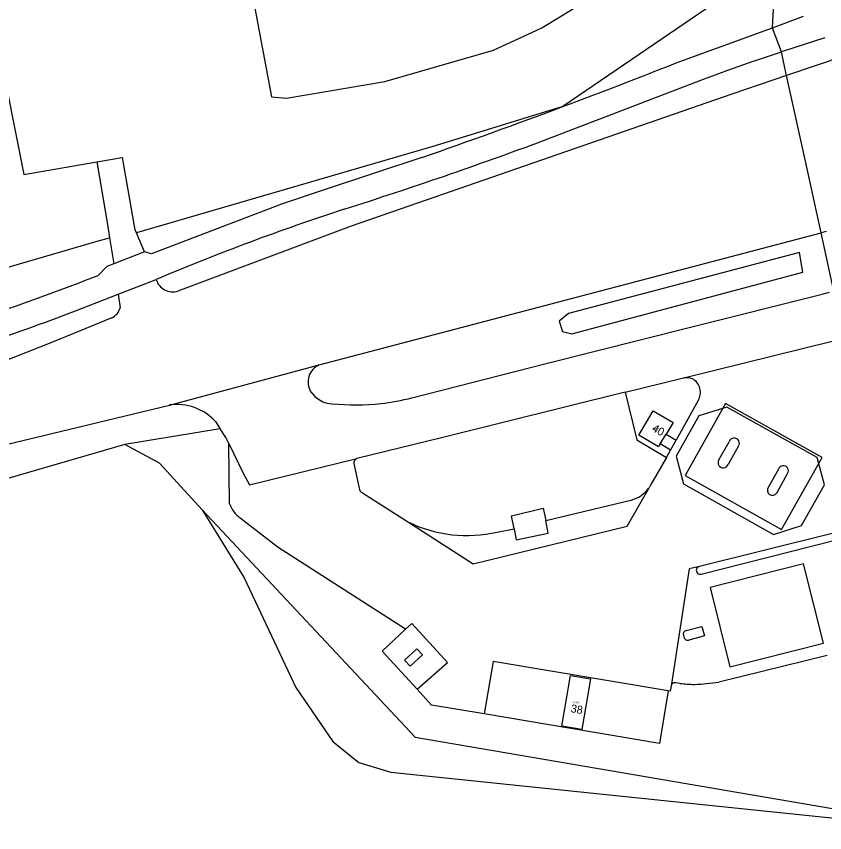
# Model space of a CAD drawing. Extents: x 124000 to 129000, y 395500 to 397503.
# Drawn here: x 124756.4 to 124856.7, y 396202 to 396303.2 of the extents above; entities that cross this region are included whole.
import ezdxf

# ---------------------------------------------------------------- set-up
doc = ezdxf.new("R2010")
doc.units = 0
for name, color, linetype in [('gg-anno-huisnummerreeks BGT', 7, 'Continuous'), ('gg-bbg-luifel en loopbrug', 7, 'Continuous'), ('gg-knt-verharding', 7, 'Continuous'), ('gg-kwrk-kunstwerk niveau 01', 7, 'Continuous'), ('gt-grn-vlakafsluiter', 7, 'Continuous'), ('gx-grn-maaiveld', 7, 'Continuous'), ('kenmerkpunt-x pandkandidaat', 7, 'Continuous')]:
    doc.layers.add(name, color=color, linetype=linetype)

msp = doc.modelspace()

# ---------------------------------------------------------------- linework, layer by layer
at = {"layer": 'gg-bbg-luifel en loopbrug'}
for points in [[(124837.26, 396219.54), (124815.51, 396223.21), (124814.41, 396216.7)], [(124826.53, 396214.76), (124824.07, 396215.17), (124825.13, 396221.46), (124827.6, 396221.05), (124826.53, 396214.76)], [(124837.26, 396219.54), (124836.16, 396213.03), (124814.41, 396216.7)]]:
    msp.add_lwpolyline(points, dxfattribs=at)
at = {"layer": 'gg-knt-verharding'}
for p, q in [((124850.18, 396301.8), (124854.06, 396303.23)), ((124856.69, 396300.56), (124851.3, 396298.84)), ((124865.47, 396300.5), (124851.95, 396295.88)), ((124856.85, 396276.55), (124856.23, 396276.39))]:
    msp.add_line(p, q, dxfattribs=at)
at = {"layer": 'gg-kwrk-kunstwerk niveau 01'}
for points in [[(124839.34, 396246.25), (124851.3, 396239.57), (124856.35, 396248.51), (124844.35, 396255.21), (124839.34, 396246.25)], [(124842.45, 396232.38), (124844.88, 396222.55), (124856.52, 396225.47), (124854.06, 396235.29), (124842.45, 396232.38)]]:
    msp.add_lwpolyline(points, dxfattribs=at)
at = {"layer": 'gt-grn-vlakafsluiter'}
msp.add_line((124857.82, 396269.12), (124856.23, 396276.39), dxfattribs=at)
at = {"layer": 'gx-grn-maaiveld'}
for p, q in [((124850.55, 396310.04), (124824.19, 396292.04)), ((124850.55, 396310.04), (124850.17, 396301.82)), ((124838.23, 396297.45), (124850.18, 396301.8)), ((124850.17, 396301.82), (124850.18, 396301.8)), ((124772.25, 396274.03), (124771.28, 396276.37)), ((124793.94, 396260), (124856.23, 396276.39)), ((124772.25, 396274.03), (124768.44, 396272.54)), ((124769.01, 396268.76), (124773.71, 396270.59)), ((124763.69, 396266.69), (124769.01, 396268.76)), ((124769.01, 396268.76), (124769.24, 396267.08)), ((124775.36, 396255.01), (124793.94, 396260)), ((124840.96, 396255.56), (124838.22, 396250.66)), ((124743.71, 396247.4), (124775.36, 396255.01)), ((124781.64, 396252.06), (124769.82, 396250.1)), ((124781.06, 396252.96), (124781.64, 396252.06)), ((124836.25, 396250.18), (124836.98, 396251.38)), ((124836.98, 396251.38), (124838.22, 396250.66)), ((124769.82, 396250.1), (124712.37, 396233.43)), ((124782.8, 396242.74), (124782.71, 396250.22)), ((124837.52, 396249.41), (124836.25, 396250.18)), ((124837.52, 396249.41), (124838.22, 396250.66)), ((124843.54, 396248.19), (124844.83, 396250.46)), ((124837.02, 396248.51), (124837.52, 396249.41)), ((124845.93, 396249.86), (124844.69, 396247.65)), ((124785.29, 396245.09), (124798.62, 396248.37)), ((124798.24, 396247.74), (124798.88, 396244.71)), ((124850.92, 396247.04), (124849.65, 396244.78)), ((124850.71, 396244.09), (124852.07, 396246.5)), ((124799.33, 396244.1), (124805.01, 396240.47)), ((124822.05, 396240.67), (124832.63, 396243.2)), ((124816.01, 396239.24), (124818.12, 396239.64)), ((124841.36, 396234.03), (124857.8, 396238.22)), ((124839.14, 396226.46), (124839.2, 396226.22)), ((124856.99, 396223.95), (124843.52, 396220.62)), ((124838.71, 396220.48), (124838.15, 396220.54))]:
    msp.add_line(p, q, dxfattribs=at)
for points in [[(124803.83, 396330.6), (124784.45, 396326.81), (124781.8, 396326.29), (124788.02, 396293.25), (124789.9, 396293.06), (124802.1, 396295.16), (124815.59, 396299.02), (124821.55, 396301.82), (124827.93, 396305.75), (124832.84, 396309.96), (124835.65, 396313.39), (124837.12, 396316.32), (124837.86, 396319.83), (124837.65, 396322.26), (124827.21, 396360.52), (124823.73, 396373.27), (124820.79, 396372.66), (124806.56, 396369.97), (124808.01, 396359.39), (124801.31, 396351.1), (124803.83, 396330.6)], [(124719.46, 396370.32), (124702.77, 396321.29), (124696.9, 396307.16), (124680.74, 396271.99), (124666.87, 396247.07), (124752.02, 396271.18), (124766.38, 396275.33), (124767.93, 396275.77)], [(124750.47, 396352.66), (124756.67, 396322.55), (124749.81, 396321.14), (124757.29, 396283.59), (124766.33, 396285.18)], [(124851.3, 396298.84), (124850.19, 396301.78), (124850.18, 396301.8)], [(124821.78, 396287.83), (124841.32, 396295.32), (124844.63, 396296.53), (124847.81, 396297.65), (124847.96, 396297.7), (124851.3, 396298.84)], [(124851.95, 396295.88), (124851.69, 396297.06), (124851.3, 396298.84)], [(124851.95, 396295.88), (124845.15, 396293.57), (124797.92, 396277.18), (124776.41, 396269.13)], [(124856.23, 396276.39), (124854.29, 396285.26), (124851.95, 396295.88)], [(124824.19, 396292.04), (124808.34, 396287.15), (124771.28, 396276.37)], [(124766.33, 396285.18), (124769.47, 396285.73), (124771.05, 396276.73), (124771.28, 396276.37)], [(124806.66, 396285.71), (124794.45, 396281.65), (124789.25, 396279.92), (124773.12, 396273.78), (124772.25, 396274.03)], [(124766.33, 396285.18), (124767.7, 396277.16), (124767.93, 396275.77)], [(124767.93, 396275.77), (124767.97, 396275.5), (124768.44, 396272.54)], [(124824.15, 396264.15), (124825.29, 396263.85), (124853.96, 396271.49), (124853.55, 396273.93), (124824.89, 396266.37), (124823.72, 396265.43), (124824.15, 396264.15)], [(124768.44, 396272.54), (124767.59, 396272.18), (124766.51, 396271.09)], [(124805.45, 396255.91), (124822.11, 396260.15), (124840.01, 396264.65), (124856.36, 396268.76), (124857.26, 396268.99)], [(124768.19, 396265.81), (124760.84, 396262.79), (124741.32, 396255.12), (124741.19, 396255.32), (124701.79, 396242.06)], [(124839.18, 396258.37), (124857.77, 396262.96), (124858.16, 396263.06)], [(124831.91, 396256.6), (124838.82, 396258.31), (124838.99, 396258.35), (124839.18, 396258.37)], [(124831.91, 396256.6), (124809.29, 396251), (124798.62, 396248.37)], [(124831.91, 396256.6), (124833.36, 396250.7), (124837.02, 396248.51)], [(124836.25, 396250.18), (124836.05, 396249.84), (124833.61, 396251.26), (124835.39, 396254.3), (124837.86, 396252.86), (124836.98, 396251.38)], [(124853.81, 396240.05), (124856.65, 396245.12), (124855.72, 396248.49), (124844.51, 396254.73), (124841.06, 396253.67), (124838.23, 396248.65), (124839.14, 396245.24), (124850.33, 396238.96), (124853.81, 396240.05)], [(124782.71, 396250.22), (124782.35, 396250.97), (124781.64, 396252.06)], [(124779.43, 396242), (124774.12, 396247.8), (124769.82, 396250.1)], [(124782.71, 396250.22), (124784.53, 396246.48), (124785.29, 396245.09)], [(124837.02, 396248.51), (124835.11, 396245.14), (124834.87, 396244.72)], [(124805.01, 396240.47), (124813.06, 396235.29), (124832.14, 396239.99), (124834.87, 396244.72)], [(124779.43, 396242), (124784.63, 396233.59), (124791.04, 396219.98), (124795.64, 396213.28), (124798.84, 396210.68), (124802.85, 396209.48), (124875.04, 396201.96)], [(124779.43, 396242), (124805.87, 396213.81), (124875.04, 396201.96)], [(124818.12, 396239.64), (124817.81, 396241.28), (124821.73, 396242.23), (124822.05, 396240.67)], [(124804.66, 396227.19), (124788.85, 396237.34), (124784.13, 396240.98)], [(124818.12, 396239.64), (124818.38, 396238.3), (124822.36, 396239.1), (124822.05, 396240.67)], [(124864.46, 396240.7), (124857.6, 396239.09), (124841.12, 396234.98)], [(124841.12, 396234.98), (124839.87, 396234.7), (124837.6, 396220.15)], [(124806.09, 396219.74), (124809.87, 396223.08), (124805.44, 396227.92), (124804.66, 396227.19)], [(124806.09, 396219.74), (124801.77, 396224.48), (124804.66, 396227.19)], [(124839.48, 396227.05), (124841.43, 396227.54), (124841.74, 396226.36), (124839.8, 396225.84)], [(124804.53, 396223.36), (124805.22, 396222.61), (124806.76, 396224.01), (124806.06, 396224.77), (124804.53, 396223.36)], [(124814.41, 396216.7), (124807.88, 396217.77), (124806.09, 396219.74)], [(124837.6, 396220.15), (124837.53, 396219.71), (124837.49, 396219.5), (124837.26, 396219.54)]]:
    msp.add_lwpolyline(points, dxfattribs=at)
for centre, radius, start, end in [((124547.77, 397030.22), 788.24, 290.5284, 291.62259), ((124529.67, 397080.85), 842.01, 289.20587, 290.47403), ((124638.52, 396780.08), 525.26, 287.5672, 290.4197), ((124891.23, 395991.76), 302.58, 108.1341, 112.8553), ((124660.02, 396543.03), 292.05, 286.1003, 291.3859), ((124775.78, 396271.2), 2.16, 196.3995, 286.9282), ((124671.62, 396506.61), 256.98, 285.1963, 290.9932), ((124767.25, 396267.66), 2.08, 297.091, 343.6728), ((124794.94, 396257.85), 2.38, 115.0036, 210.0504), ((124839.45, 396255.84), 2.54, 71.7233, 96.0912), ((124839.36, 396256.59), 1.89, 327.1752, 62.1218), ((124795.68, 396258.53), 3.36, 213.8217, 268.0727), ((124776.27, 396248.58), 6.5, 42.4478, 98.064), ((124798.5, 396283.82), 28.8, 264.1479, 276.1749), ((124798.36, 396283.06), 28.06, 276.6217, 284.6409), ((124845.44, 396250.27), 0.642, 319.6834, 163.0303), ((124798.77, 396247.85), 0.541, 106.6615, 192.1862), ((124844.08, 396247.85), 0.639, 147.6704, 341.663), ((124851.53, 396246.84), 0.64, 327.7899, 161.6207), ((124799.59, 396244.76), 0.707, 184.2132, 249.0426), ((124831.62, 396247.11), 4.03, 284.5835, 323.6794), ((124850.18, 396244.44), 0.634, 147.1843, 326.2871), ((124786.84, 396244.41), 4.37, 202.3732, 231.6774), ((124812.28, 396255.56), 16.74, 244.2901, 282.8831), ((124841.23, 396234.5), 0.491, 102.929, 285.2567), ((124839.6, 396226.58), 0.48, 104.8645, 194.3419), ((124839.68, 396226.31), 0.483, 191.5029, 284.7801), ((124838.08, 396220.06), 0.483, 80.6104, 169.9546), ((124841.17, 396241.05), 20.72, 263.2002, 268.1545), ((124838.04, 396263.08), 42.81, 273.2994, 277.3629)]:
    msp.add_arc(centre, radius, start, end, dxfattribs=at)

# ---------------------------------------------------------------- texts
at = {"layer": 'gg-anno-huisnummerreeks BGT'}
for s, rotation, p in [('40', 329.7, (124835.13, 396251.85)), ('38', 350.4, (124825.1, 396216.91))]:
    msp.add_text(s, height=1, rotation=rotation, dxfattribs=at).set_placement(p)
at = {"layer": 'kenmerkpunt-x pandkandidaat'}
for p in [(124835.37, 396251.96), (124825.46, 396218.01)]:
    msp.add_text('PNDK', height=0.2, dxfattribs=at).set_placement(p)

doc.saveas('drawing.dxf')
